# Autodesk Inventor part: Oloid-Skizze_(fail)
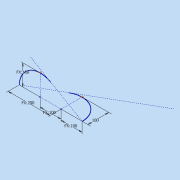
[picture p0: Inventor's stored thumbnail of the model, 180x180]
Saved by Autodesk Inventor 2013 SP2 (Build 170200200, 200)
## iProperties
Created: 2014-11
Part Number: Oloid-Skizze_(fail)
Material: Allgemein
Document SubType Name: Modeling
Designer: Besitzer
Density: 1 g/cm^3
Author: Besitzer
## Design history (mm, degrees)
sketch "Skizze1"
  geometry: L1 (-200, 0)-(0, 0); L2 (0, 0)-(0, 100); L3 (-200, 0)-(267.223, 269.752); A1 r 100 centre (0, 0) between (100, 0) and (-50, 86.603); 1 further point
  constraints: 6 end point, 3 point on circle, 2 coincident, 2 point on line, 1 centre point, 1 horizontal, 1 perpendicular, 1 tangent
  dimensions: "Radius" = 100 distance of L1.end L2.end; "d6" = 200 distance of L1.start L1.end (= 2 x Radius)
workpoint "Arbeitspunkt1"
sketch "Skizze2"
  geometry: L1 (100, 0)-(-100, 0); L2 (-100, 0)-(144.975, 141.436); L3 (100, 0)-(100, 100); A1 r 100 centre (100, 0) between (200, 0) and (50, 86.603); 1 further point
  constraints: 6 end point, 3 point on circle, 2 point on line, 1 centre point, 1 coincident, 1 horizontal, 1 midpoint, 1 perpendicular, 1 tangent
  dimensions: "d7" = 100 distance of L1.start L3.end (= Radius); "d9" = 100 distance from line of point (0, 0) L3 (= Radius); "d10" = 100 distance of L1.end point (0, 0) (= Radius)
workpoint "Arbeitspunkt2"
